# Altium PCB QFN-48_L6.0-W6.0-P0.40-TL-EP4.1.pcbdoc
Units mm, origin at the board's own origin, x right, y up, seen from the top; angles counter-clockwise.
Board outline 19.6 x 19.18 mm, 2 copper layers (Top Layer, Bottom Layer), stack 0 mm thick; 1 components, 0 nets, 49 pads, 0 vias.
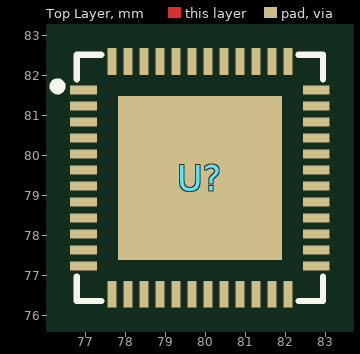
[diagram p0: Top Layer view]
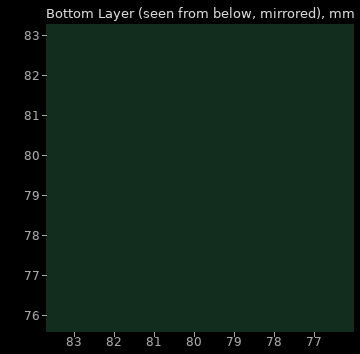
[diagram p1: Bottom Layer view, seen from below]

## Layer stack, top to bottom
Top Layer: signal copper (thickness not stored)
Bottom Layer: signal copper (thickness not stored)

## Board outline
89.446,69.85 69.85,69.85 69.85,89.03 89.446,89.03

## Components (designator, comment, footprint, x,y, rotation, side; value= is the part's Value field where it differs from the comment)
U? "" QFN-48_L6.0-W6.0-P0.40-TL-EP4.1 79.856,79.44 r0 top

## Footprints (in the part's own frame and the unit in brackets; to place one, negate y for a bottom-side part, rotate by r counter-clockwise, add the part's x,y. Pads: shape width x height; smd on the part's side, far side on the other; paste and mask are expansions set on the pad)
QFN-48_L6.0-W6.0-P0.40-TL-EP4.1 [mm]
  rect 0.665x0.224 smd paste-100 mask+0.051: 1(-2.908,2.2) 2(-2.908,1.8) 3(-2.908,1.4) 4(-2.908,1) 5(-2.908,0.6) 6(-2.908,0.2) 7(-2.908,-0.2) 8(-2.908,-0.6) 9(-2.908,-1) 10(-2.908,-1.4) 11(-2.908,-1.8) 12(-2.908,-2.2) 25(2.908,-2.2) 26(2.908,-1.8) 27(2.908,-1.4) 28(2.908,-1) 29(2.908,-0.6) 30(2.908,-0.2) 31(2.908,0.2) 32(2.908,0.6) 33(2.908,1) 34(2.908,1.4) 35(2.908,1.8) 36(2.908,2.2)
  rect 0.224x0.665 smd paste-100 mask+0.051: 13(-2.2,-2.908) 14(-1.8,-2.908) 15(-1.4,-2.908) 16(-1,-2.908) 17(-0.6,-2.908) 18(-0.2,-2.908) 19(0.2,-2.908) 20(0.6,-2.908) 21(1,-2.908) 22(1.4,-2.908) 23(1.8,-2.908) 24(2.2,-2.908) 37(2.2,2.908) 38(1.8,2.908) 39(1.4,2.908) 40(1,2.908) 41(0.6,2.908) 42(0.2,2.908) 43(-0.2,2.908) 44(-0.6,2.908) 45(-1,2.908) 46(-1.4,2.908) 47(-1.8,2.908) 48(-2.2,2.908)
  rect 4.1x4.1 smd paste-100 mask+0.051: 49(0,0)
  silkscreen extent -3.66,-3.08 3.08,3.08

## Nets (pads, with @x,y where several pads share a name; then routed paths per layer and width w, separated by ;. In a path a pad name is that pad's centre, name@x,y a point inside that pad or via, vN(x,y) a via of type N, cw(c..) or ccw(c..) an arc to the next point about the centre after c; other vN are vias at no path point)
pads on no net: U?.1 U?.2 U?.3 U?.4 U?.5 U?.6 U?.7 U?.8 U?.9 U?.10 U?.11 U?.12 U?.13 U?.14 U?.15 U?.16 U?.17 U?.18 U?.19 U?.20 U?.21 U?.22 U?.23 U?.24 U?.25 U?.26 U?.27 U?.28 U?.29 U?.30 U?.31 U?.32 U?.33 U?.34 U?.35 U?.36 U?.37 U?.38 U?.39 U?.40 U?.41 U?.42 U?.43 U?.44 U?.45 U?.46 U?.47 U?.48 U?.49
